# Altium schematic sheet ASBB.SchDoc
size A4
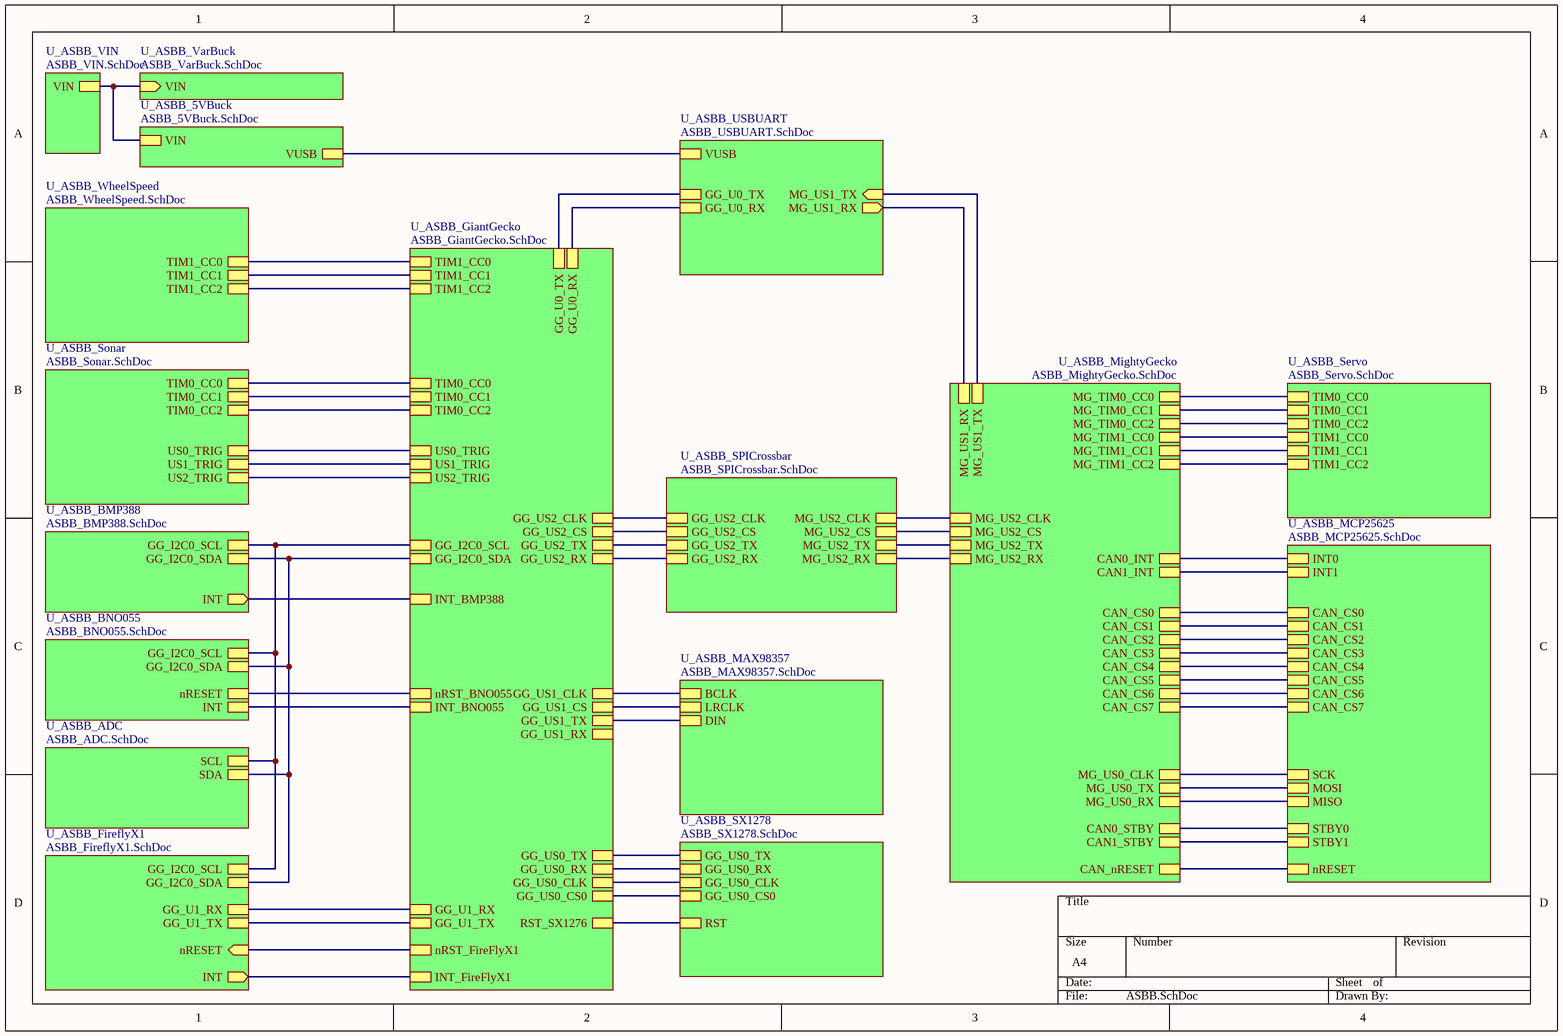
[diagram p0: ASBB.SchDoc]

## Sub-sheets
U_ASBB_5VBuck = ASBB_5VBuck.SchDoc: VIN, VUSB
U_ASBB_ADC = ASBB_ADC.SchDoc: SDA, SCL
U_ASBB_BMP388 = ASBB_BMP388.SchDoc: INT (out), GG_I2C0_SCL, GG_I2C0_SDA
U_ASBB_BNO055 = ASBB_BNO055.SchDoc: INT, GG_I2C0_SCL, GG_I2C0_SDA, nRESET
U_ASBB_FireflyX1 = ASBB_FireflyX1.SchDoc: INT (out), nRESET (in), GG_U1_TX, GG_I2C0_SCL, GG_U1_RX, GG_I2C0_SDA
U_ASBB_GiantGecko = ASBB_GiantGecko.SchDoc: GG_U0_TX, GG_US1_CLK, GG_US0_CS0, GG_US2_RX, GG_U1_RX, GG_US2_CLK, GG_US1_TX, GG_US0_TX, GG_US2_TX, GG_US1_RX, GG_I2C0_SDA, GG_U1_TX, GG_US2_CS, GG_U0_RX, GG_US0_RX, GG_US1_CS, GG_US0_CLK, GG_I2C0_SCL, INT_BNO055, INT_BMP388, nRST_FireFlyX1, INT_FireFlyX1, RST_SX1276, TIM1_CC1, TIM0_CC0, TIM1_CC0, TIM0_CC2, TIM1_CC2, TIM0_CC1, US2_TRIG, US1_TRIG, US0_TRIG, nRST_BNO055
U_ASBB_MAX98357 = ASBB_MAX98357.SchDoc: BCLK, LRCLK, DIN
U_ASBB_MCP25625 = ASBB_MCP25625.SchDoc: INT0, INT1, SCK, MOSI, MISO, STBY1, STBY0, nRESET, CAN_CS7, CAN_CS1, CAN_CS4, CAN_CS5, CAN_CS0, CAN_CS3, CAN_CS6, CAN_CS2
U_ASBB_MightyGecko = ASBB_MightyGecko.SchDoc: MG_US0_CLK, MG_US0_RX, MG_US0_TX, MG_US2_CLK, MG_US2_RX, MG_US2_TX, MG_US2_CS, MG_US1_RX, MG_US1_TX, MG_TIM0_CC0, MG_TIM1_CC0, MG_TIM0_CC1, MG_TIM0_CC2, CAN1_INT, CAN0_STBY, CAN_nRESET, CAN0_INT, CAN1_STBY, MG_TIM1_CC1, MG_TIM1_CC2, CAN_CS1, CAN_CS0, CAN_CS6, CAN_CS2, CAN_CS4, CAN_CS7, CAN_CS5, CAN_CS3
U_ASBB_Servo = ASBB_Servo.SchDoc: TIM0_CC0, TIM0_CC1, TIM0_CC2, TIM1_CC0, TIM1_CC1, TIM1_CC2
U_ASBB_Sonar = ASBB_Sonar.SchDoc: TIM0_CC0, US0_TRIG, TIM0_CC1, US1_TRIG, TIM0_CC2, US2_TRIG
U_ASBB_SPICrossbar = ASBB_SPICrossbar.SchDoc: GG_US2_CLK, GG_US2_TX, GG_US2_CS, MG_US2_CLK, MG_US2_TX, MG_US2_RX, MG_US2_CS, GG_US2_RX
U_ASBB_SX1278 = ASBB_SX1278.SchDoc: RST, GG_US0_TX, GG_US0_RX, GG_US0_CLK, GG_US0_CS0
U_ASBB_USBUART = ASBB_USBUART.SchDoc: GG_U0_TX, GG_U0_RX, MG_US1_TX (in), MG_US1_RX (out), VUSB
U_ASBB_VarBuck = ASBB_VarBuck.SchDoc: VIN (in)
U_ASBB_VIN = ASBB_VIN.SchDoc: VIN
U_ASBB_WheelSpeed = ASBB_WheelSpeed.SchDoc: TIM1_CC0, TIM1_CC1, TIM1_CC2

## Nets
(unnamed): sheet U_ASBB_VarBuck/VIN, sheet U_ASBB_5VBuck/VIN, sheet U_ASBB_VIN/VIN
(unnamed): sheet U_ASBB_5VBuck/VUSB, sheet U_ASBB_USBUART/VUSB  [a separate net that carries the same name]
(unnamed): sheet U_ASBB_USBUART/GG_U0_TX, sheet U_ASBB_GiantGecko/GG_U0_TX  [a separate net that carries the same name]
(unnamed): sheet U_ASBB_USBUART/GG_U0_RX, sheet U_ASBB_GiantGecko/GG_U0_RX  [a separate net that carries the same name]
(unnamed): sheet U_ASBB_USBUART/MG_US1_TX, sheet U_ASBB_MightyGecko/MG_US1_TX  [a separate net that carries the same name]
(unnamed): sheet U_ASBB_USBUART/MG_US1_RX, sheet U_ASBB_MightyGecko/MG_US1_RX  [a separate net that carries the same name]
(unnamed): sheet U_ASBB_BMP388/INT, sheet U_ASBB_GiantGecko/INT_BMP388  [a separate net that carries the same name]
(unnamed): sheet U_ASBB_BMP388/GG_I2C0_SCL, sheet U_ASBB_BNO055/GG_I2C0_SCL, sheet U_ASBB_FireflyX1/GG_I2C0_SCL, sheet U_ASBB_GiantGecko/GG_I2C0_SCL, sheet U_ASBB_ADC/SCL  [a separate net that carries the same name]
(unnamed): sheet U_ASBB_BMP388/GG_I2C0_SDA, sheet U_ASBB_BNO055/GG_I2C0_SDA, sheet U_ASBB_FireflyX1/GG_I2C0_SDA, sheet U_ASBB_GiantGecko/GG_I2C0_SDA, sheet U_ASBB_ADC/SDA  [a separate net that carries the same name]
(unnamed): sheet U_ASBB_BNO055/INT, sheet U_ASBB_GiantGecko/INT_BNO055  [a separate net that carries the same name]
(unnamed): sheet U_ASBB_BNO055/nRESET, sheet U_ASBB_GiantGecko/nRST_BNO055  [a separate net that carries the same name]
(unnamed): sheet U_ASBB_MAX98357/BCLK, sheet U_ASBB_GiantGecko/GG_US1_CLK  [a separate net that carries the same name]
(unnamed): sheet U_ASBB_MAX98357/LRCLK, sheet U_ASBB_GiantGecko/GG_US1_CS  [a separate net that carries the same name]
(unnamed): sheet U_ASBB_MAX98357/DIN, sheet U_ASBB_GiantGecko/GG_US1_TX  [a separate net that carries the same name]
(unnamed): sheet U_ASBB_MCP25625/INT0, sheet U_ASBB_MightyGecko/CAN0_INT  [a separate net that carries the same name]
(unnamed): sheet U_ASBB_MCP25625/INT1, sheet U_ASBB_MightyGecko/CAN1_INT  [a separate net that carries the same name]
(unnamed): sheet U_ASBB_MCP25625/SCK, sheet U_ASBB_MightyGecko/MG_US0_CLK  [a separate net that carries the same name]
(unnamed): sheet U_ASBB_MCP25625/MOSI, sheet U_ASBB_MightyGecko/MG_US0_TX  [a separate net that carries the same name]
(unnamed): sheet U_ASBB_MCP25625/MISO, sheet U_ASBB_MightyGecko/MG_US0_RX  [a separate net that carries the same name]
(unnamed): sheet U_ASBB_MCP25625/STBY1, sheet U_ASBB_MightyGecko/CAN1_STBY  [a separate net that carries the same name]
(unnamed): sheet U_ASBB_MCP25625/STBY0, sheet U_ASBB_MightyGecko/CAN0_STBY  [a separate net that carries the same name]
(unnamed): sheet U_ASBB_MCP25625/nRESET, sheet U_ASBB_MightyGecko/CAN_nRESET  [a separate net that carries the same name]
(unnamed): sheet U_ASBB_MCP25625/CAN_CS7, sheet U_ASBB_MightyGecko/CAN_CS7  [a separate net that carries the same name]
(unnamed): sheet U_ASBB_MCP25625/CAN_CS1, sheet U_ASBB_MightyGecko/CAN_CS1  [a separate net that carries the same name]
(unnamed): sheet U_ASBB_MCP25625/CAN_CS4, sheet U_ASBB_MightyGecko/CAN_CS4  [a separate net that carries the same name]
(unnamed): sheet U_ASBB_MCP25625/CAN_CS5, sheet U_ASBB_MightyGecko/CAN_CS5  [a separate net that carries the same name]
(unnamed): sheet U_ASBB_MCP25625/CAN_CS0, sheet U_ASBB_MightyGecko/CAN_CS0  [a separate net that carries the same name]
(unnamed): sheet U_ASBB_MCP25625/CAN_CS3, sheet U_ASBB_MightyGecko/CAN_CS3  [a separate net that carries the same name]
(unnamed): sheet U_ASBB_MCP25625/CAN_CS6, sheet U_ASBB_MightyGecko/CAN_CS6  [a separate net that carries the same name]
(unnamed): sheet U_ASBB_MCP25625/CAN_CS2, sheet U_ASBB_MightyGecko/CAN_CS2  [a separate net that carries the same name]
(unnamed): sheet U_ASBB_FireflyX1/INT, sheet U_ASBB_GiantGecko/INT_FireFlyX1  [a separate net that carries the same name]
(unnamed): sheet U_ASBB_FireflyX1/nRESET, sheet U_ASBB_GiantGecko/nRST_FireFlyX1  [a separate net that carries the same name]
(unnamed): sheet U_ASBB_FireflyX1/GG_U1_TX, sheet U_ASBB_GiantGecko/GG_U1_TX  [a separate net that carries the same name]
(unnamed): sheet U_ASBB_FireflyX1/GG_U1_RX, sheet U_ASBB_GiantGecko/GG_U1_RX  [a separate net that carries the same name]
(unnamed): sheet U_ASBB_SX1278/RST, sheet U_ASBB_GiantGecko/RST_SX1276  [a separate net that carries the same name]
(unnamed): sheet U_ASBB_SX1278/GG_US0_TX, sheet U_ASBB_GiantGecko/GG_US0_TX  [a separate net that carries the same name]
(unnamed): sheet U_ASBB_SX1278/GG_US0_RX, sheet U_ASBB_GiantGecko/GG_US0_RX  [a separate net that carries the same name]
(unnamed): sheet U_ASBB_SX1278/GG_US0_CLK, sheet U_ASBB_GiantGecko/GG_US0_CLK  [a separate net that carries the same name]
(unnamed): sheet U_ASBB_SX1278/GG_US0_CS0, sheet U_ASBB_GiantGecko/GG_US0_CS0  [a separate net that carries the same name]
(unnamed): sheet U_ASBB_GiantGecko/GG_US2_RX, sheet U_ASBB_SPICrossbar/GG_US2_RX  [a separate net that carries the same name]
(unnamed): sheet U_ASBB_GiantGecko/GG_US2_CLK, sheet U_ASBB_SPICrossbar/GG_US2_CLK  [a separate net that carries the same name]
(unnamed): sheet U_ASBB_GiantGecko/GG_US2_TX, sheet U_ASBB_SPICrossbar/GG_US2_TX  [a separate net that carries the same name]
(unnamed): sheet U_ASBB_GiantGecko/GG_US2_CS, sheet U_ASBB_SPICrossbar/GG_US2_CS  [a separate net that carries the same name]
(unnamed): sheet U_ASBB_GiantGecko/TIM1_CC1, sheet U_ASBB_WheelSpeed/TIM1_CC1  [a separate net that carries the same name]
(unnamed): sheet U_ASBB_GiantGecko/TIM0_CC0, sheet U_ASBB_Sonar/TIM0_CC0  [a separate net that carries the same name]
(unnamed): sheet U_ASBB_GiantGecko/TIM1_CC0, sheet U_ASBB_WheelSpeed/TIM1_CC0  [a separate net that carries the same name]
(unnamed): sheet U_ASBB_GiantGecko/TIM0_CC2, sheet U_ASBB_Sonar/TIM0_CC2  [a separate net that carries the same name]
(unnamed): sheet U_ASBB_GiantGecko/TIM1_CC2, sheet U_ASBB_WheelSpeed/TIM1_CC2  [a separate net that carries the same name]
(unnamed): sheet U_ASBB_GiantGecko/TIM0_CC1, sheet U_ASBB_Sonar/TIM0_CC1  [a separate net that carries the same name]
(unnamed): sheet U_ASBB_GiantGecko/US2_TRIG, sheet U_ASBB_Sonar/US2_TRIG  [a separate net that carries the same name]
(unnamed): sheet U_ASBB_GiantGecko/US1_TRIG, sheet U_ASBB_Sonar/US1_TRIG  [a separate net that carries the same name]
(unnamed): sheet U_ASBB_GiantGecko/US0_TRIG, sheet U_ASBB_Sonar/US0_TRIG  [a separate net that carries the same name]
(unnamed): sheet U_ASBB_Servo/TIM0_CC0, sheet U_ASBB_MightyGecko/MG_TIM0_CC0  [a separate net that carries the same name]
(unnamed): sheet U_ASBB_Servo/TIM0_CC1, sheet U_ASBB_MightyGecko/MG_TIM0_CC1  [a separate net that carries the same name]
(unnamed): sheet U_ASBB_Servo/TIM0_CC2, sheet U_ASBB_MightyGecko/MG_TIM0_CC2  [a separate net that carries the same name]
(unnamed): sheet U_ASBB_Servo/TIM1_CC0, sheet U_ASBB_MightyGecko/MG_TIM1_CC0  [a separate net that carries the same name]
(unnamed): sheet U_ASBB_Servo/TIM1_CC1, sheet U_ASBB_MightyGecko/MG_TIM1_CC1  [a separate net that carries the same name]
(unnamed): sheet U_ASBB_Servo/TIM1_CC2, sheet U_ASBB_MightyGecko/MG_TIM1_CC2  [a separate net that carries the same name]
(unnamed): sheet U_ASBB_MightyGecko/MG_US2_CLK, sheet U_ASBB_SPICrossbar/MG_US2_CLK  [a separate net that carries the same name]
(unnamed): sheet U_ASBB_MightyGecko/MG_US2_RX, sheet U_ASBB_SPICrossbar/MG_US2_RX  [a separate net that carries the same name]
(unnamed): sheet U_ASBB_MightyGecko/MG_US2_TX, sheet U_ASBB_SPICrossbar/MG_US2_TX  [a separate net that carries the same name]
(unnamed): sheet U_ASBB_MightyGecko/MG_US2_CS, sheet U_ASBB_SPICrossbar/MG_US2_CS  [a separate net that carries the same name]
